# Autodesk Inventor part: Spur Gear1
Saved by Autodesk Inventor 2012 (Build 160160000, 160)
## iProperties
Created: 2018-05
Part Number: Spur Gear1
Material: Steel
Document SubType Name: Modeling
Designer: Elkawokgy
Categories: <?xml version="1.0" encoding="UTF-16"?> <MemberInstance><Categories><FamilyTemplate><FamilyTemplateParameter ValueType="xs:double" Id="1" ObjectReferenceKey="da
Density: 1 g/cm^3
CustomPartVersion: 1
Author: Elkawokgy
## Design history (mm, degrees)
sketch "Sketch1"
  geometry: C1 r 6.3 at (0, 0)
  constraints: 1 centre point
  dimensions: "d0" = 12.6 diameter of C1 (= da_da)
extrude "Extrusion1" new body sketch "Sketch1" distance "d1" = 5 (= da_b); taper "d2" = 0 deg
workplane "Work Plane2"
sketch "Sketch2"
  geometry: C1 r 6.3 at (0, 0) reference; C2 r 4.725 at (0, 0)
  constraints: 1 centre point, 1 coincident
  dimensions: "d3" = 9.45 diameter of C2 (= da_dw)
feature "Pitch Diameter" sketch "Sketch2" dims "d4" = 10, "d5" = 0
workplane "Work Plane8"
workplane "Work Plane9"
feature "Spur Gear" dims "da_b" = 5, "da_d" = 9.45, "da_aw" = 57.225, "da_da" = 12.6, "da_df" = 7.875, "da_dw" = 9.45, angle "da_beta" = 0 deg, "da_lefttooth" = 0, "da_righttooth" = 0
body "Solid1"
body "Srf1"
other parameters: "d16" = 57.225 (= da_aw), "d17" = 0, "d34" = 20 deg (computed from da_z), "d39" = 0, "d41" = 0, "d43" = 57.225 (= da_aw), "d46" = 57.225 (= da_aw), "d47" = 0, "d48" = 0
